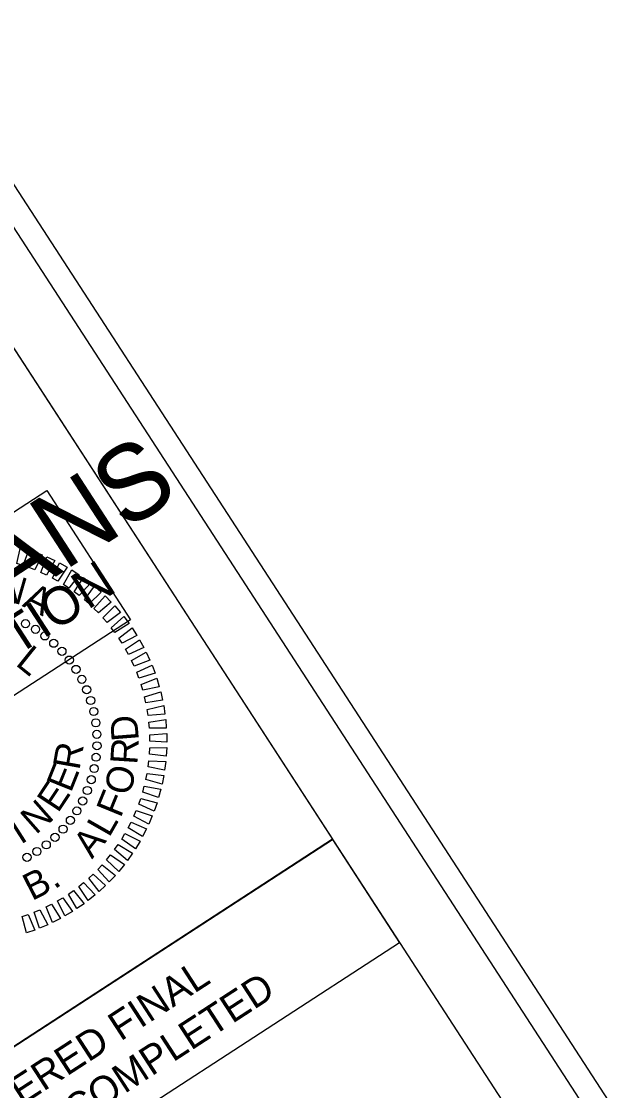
# Model space of a CAD drawing. Extents: x 555170 to 557181, y 503234 to 505074.
# Drawn here: x 556603.6 to 556715, y 504870 to 505074 of the extents above; entities that cross this region are included whole.
import ezdxf

# ---------------------------------------------------------------- set-up
doc = ezdxf.new("R2010")
doc.units = 0
for name, color, linetype in [('Default', 7, 'Continuous'), ('Sheet Border Standard 30in CELL', 7, 'Continuous'), ('Sheet Plot Border Inside CELL', 7, 'Continuous'), ('Sheet Plot Border Outside CELL', 7, 'Continuous'), ('Sheet Sticker Exception Certification CELL', 7, 'Continuous'), ('Sheet Sticker Incomplete CELL', 7, 'Continuous')]:
    doc.layers.add(name, color=color, linetype=linetype)

msp = doc.modelspace()

# ---------------------------------------------------------------- linework, layer by layer
at = {"layer": 'Default'}
for points in [[(556602.76, 504970.56), (556603.48, 504973.71), (556605.07, 504973.19), (556603.89, 504970.21)], [(556605.1, 504969.79), (556606.03, 504972.88), (556607.58, 504972.25), (556606.2, 504969.37)], [(556607.37, 504968.86), (556608.52, 504971.88), (556610.02, 504971.15), (556608.45, 504968.37)], [(556609.58, 504967.78), (556610.93, 504970.71), (556612.38, 504969.87), (556610.62, 504967.21)], [(556611.7, 504966.54), (556613.26, 504969.38), (556614.65, 504968.44), (556612.7, 504965.9)], [(556613.74, 504965.16), (556615.49, 504967.88), (556616.81, 504966.84), (556614.69, 504964.45)], [(556615.67, 504963.64), (556617.61, 504966.23), (556618.85, 504965.11), (556616.57, 504962.87)], [(556617.49, 504961.99), (556619.61, 504964.44), (556620.77, 504963.23), (556618.33, 504961.16)], [(556619.2, 504960.22), (556621.47, 504962.51), (556622.55, 504961.23), (556619.98, 504959.33)], [(556620.77, 504958.33), (556623.2, 504960.46), (556624.18, 504959.1), (556621.49, 504957.39)], [(556622.21, 504956.34), (556624.78, 504958.29), (556625.67, 504956.87), (556622.86, 504955.35)], [(556623.51, 504954.25), (556626.21, 504956.02), (556626.99, 504954.54), (556624.08, 504953.22)], [(556624.65, 504952.08), (556627.48, 504953.65), (556628.15, 504952.12), (556625.16, 504951)], [(556625.65, 504949.83), (556628.57, 504951.2), (556629.14, 504949.63), (556626.08, 504948.72)], [(556626.48, 504947.51), (556629.49, 504948.68), (556629.95, 504947.07), (556626.83, 504946.38)], [(556627.15, 504945.15), (556630.24, 504946.11), (556630.58, 504944.47), (556627.42, 504944)], [(556627.65, 504942.74), (556630.8, 504943.48), (556631.03, 504941.82), (556627.85, 504941.57)], [(556627.99, 504940.31), (556631.18, 504940.83), (556631.29, 504939.16), (556628.1, 504939.13)], [(556628.15, 504937.86), (556631.37, 504938.15), (556631.37, 504936.47), (556628.18, 504936.67)], [(556628.15, 504935.4), (556631.38, 504935.47), (556631.26, 504933.8), (556628.09, 504934.21)], [(556627.97, 504932.95), (556631.2, 504932.79), (556630.96, 504931.13), (556627.83, 504931.77)], [(556627.62, 504930.51), (556630.83, 504930.13), (556630.48, 504928.49), (556627.4, 504929.35)], [(556627.1, 504928.11), (556630.28, 504927.5), (556629.81, 504925.9), (556626.8, 504926.96)], [(556626.42, 504925.75), (556629.54, 504924.92), (556628.97, 504923.35), (556626.04, 504924.63)], [(556625.57, 504923.44), (556628.63, 504922.4), (556627.94, 504920.87), (556625.11, 504922.35)], [(556624.56, 504921.2), (556627.54, 504919.95), (556626.75, 504918.47), (556624.03, 504920.14)], [(556623.4, 504919.03), (556626.29, 504917.57), (556625.4, 504916.16), (556622.8, 504918.01)], [(556622.09, 504916.95), (556624.87, 504915.3), (556623.88, 504913.94), (556621.42, 504915.98)], [(556620.64, 504914.97), (556623.3, 504913.12), (556622.22, 504911.84), (556619.9, 504914.04)], [(556619.06, 504913.09), (556621.58, 504911.06), (556620.41, 504909.86), (556618.25, 504912.22)], [(556617.34, 504911.32), (556619.72, 504909.13), (556618.47, 504908.01), (556616.48, 504910.51)], [(556613.57, 504908.18), (556615.62, 504905.67), (556614.22, 504904.74), (556612.6, 504907.49)], [(556615.51, 504909.68), (556617.73, 504907.33), (556616.4, 504906.3), (556614.6, 504908.94)], [(556611.53, 504906.81), (556613.39, 504904.17), (556611.94, 504903.33), (556610.52, 504906.19)], [(556607.18, 504904.51), (556608.66, 504901.64), (556607.11, 504901.02), (556606.1, 504904.05)], [(556609.4, 504905.59), (556611.07, 504902.82), (556609.57, 504902.09), (556608.34, 504905.04)], [(556604.9, 504903.6), (556606.18, 504900.63), (556604.58, 504900.12), (556603.78, 504903.21)]]:
    msp.add_lwpolyline(points, close=True, dxfattribs=at)
for centre in [(556604.41, 504959.09), (556606.32, 504958.01), (556608.12, 504956.76), (556609.81, 504955.36), (556611.37, 504953.82), (556612.79, 504952.15), (556614.06, 504950.37), (556615.17, 504948.48), (556616.1, 504946.49), (556616.87, 504944.44), (556617.45, 504942.33), (556617.84, 504940.17), (556618.05, 504937.99), (556618.06, 504935.8), (556617.89, 504933.61), (556617.52, 504931.45), (556616.97, 504929.33), (556616.23, 504927.26), (556615.32, 504925.27), (556614.23, 504923.37), (556611.59, 504919.88), (556612.99, 504921.56), (556610.05, 504918.32), (556606.59, 504915.63), (556608.38, 504916.9), (556604.7, 504914.52)]:
    msp.add_circle(centre, 0.777, dxfattribs=at)
at = {"layer": 'Sheet Border Standard 30in CELL'}
for points in [[(556581.3, 505043.79), (555323.3, 504226.82), (555895.18, 503346.22), (557153.18, 504163.19)], [(556517.88, 504957.83), (556601.75, 505012.3), (556663.02, 504917.95), (556579.16, 504863.48)]]:
    msp.add_lwpolyline(points, close=True, dxfattribs=at)
at = {"layer": 'Sheet Plot Border Inside CELL'}
msp.add_lwpolyline([(556590.39, 505052.74), (555192.76, 504145.08), (555767.42, 503260.21), (557165.05, 504167.86)], close=True, dxfattribs=at)
at = {"layer": 'Sheet Plot Border Outside CELL'}
msp.add_lwpolyline([(556581.94, 505074.02), (555169.63, 504156.83), (555768.74, 503234.3), (557181.05, 504151.49)], close=True, dxfattribs=at)
at = {"layer": 'Sheet Sticker Exception Certification CELL'}
for p, q in [((556495.25, 504808.99), (556663.01, 504917.94)), ((556663.02, 504917.93), (556675.82, 504898.22)), ((556675.81, 504898.23), (556508.05, 504789.28))]:
    msp.add_line(p, q, dxfattribs=at)
at = {"layer": 'Sheet Sticker Incomplete CELL'}
msp.add_lwpolyline([(556470.36, 504859.78), (556454.37, 504884.41), (556608.47, 504984.49), (556624.47, 504959.85)], close=True, dxfattribs=at)

# ---------------------------------------------------------------- texts
at = {"layer": 'Default'}
for s, rotation, p in [('N', 343.9406, (556598.91, 504963.99)), ('A', 333.7302, (556603.65, 504962.5)), ('L', 321.2259, (556602.33, 504951.29)), ('D', 94.5707, (556626.07, 504936.86)), ('R', 86.3621, (556625.75, 504932.13)), ('R', 79.9132, (556614.7, 504931.02)), ('E', 68.151, (556613.08, 504926.71)), ('O', 75.6369, (556624.33, 504926.11)), ('E', 56.3887, (556610.61, 504922.82)), ('F', 67.7142, (556622.56, 504921.88)), ('N', 41.3387, (556606.39, 504918.71)), ('I', 32.5832, (556603.49, 504916.87)), ('L', 60.2491, (556620.38, 504918.16)), ('A', 51.2016, (556617.12, 504914.08)), ('B', 26.8902, (556605.65, 504906.14)), ('.', 35.2323, (556609.96, 504908.31))]:
    msp.add_text(s, height=5.18, rotation=rotation, dxfattribs=at).set_placement(p)
at = {"layer": 'Sheet Sticker Exception Certification CELL'}
for s, p in [('DOCUMENT NOT CONSIDERED FINAL', (556527.64, 504817.69)), ('UNLESS ALL SIGNATURES COMPLETED', (556533.17, 504810.79))]:
    msp.add_text(s, height=5.5, rotation=33.0007, dxfattribs=at).set_placement(p)
at = {"layer": 'Sheet Sticker Incomplete CELL'}
for s, height, p in [('INCOMPLETE PLANS', 14.4, (556471.79, 504878.16)), ('DO NOT USE FOR R/W ACQUISITION', 7.2, (556479.92, 504873.08))]:
    msp.add_text(s, height=height, rotation=33.0007, dxfattribs=at).set_placement(p)

doc.saveas('drawing.dxf')
